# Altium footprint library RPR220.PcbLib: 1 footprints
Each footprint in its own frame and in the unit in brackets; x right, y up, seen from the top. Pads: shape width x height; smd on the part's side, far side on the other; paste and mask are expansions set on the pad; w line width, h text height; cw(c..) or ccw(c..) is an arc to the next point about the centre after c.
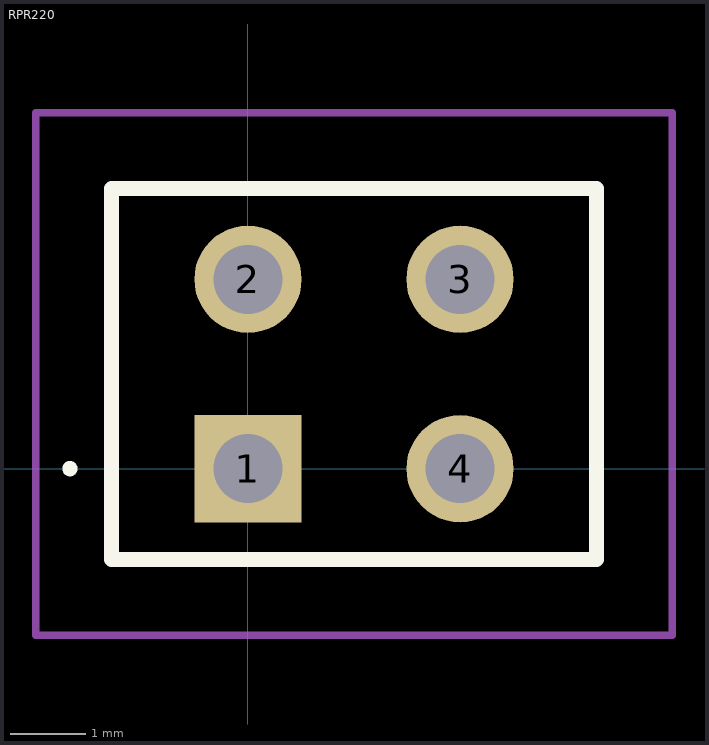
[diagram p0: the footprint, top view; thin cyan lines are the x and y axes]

## RPR220 [mm]
pads (4):
  rect 1.416x1.416 hole 0.91: 1(0,0)
  round 1.416 hole 0.91: 2(0,2.5) 3(2.8,2.5) 4(2.8,0)
Top Overlay:
  lines w0.1: -2.4,0 cw(c-2.35,0) -2.3,0 ; -2.4,0 -2.4,0 ; -2.4,0 ccw(c-2.35,0) -2.3,0 ; -2.3,0 -2.3,0
  lines w0.2: -1.8,-1.2 4.6,-1.2 4.6,3.7 -1.8,3.7 -1.8,-1.2
Mechanical 15:
  lines w0.1: -1.8,-1.2 4.6,-1.2 4.6,3.7 -1.8,3.7 -1.8,-1.2
Mechanical 20:
  lines w0.1: -2.8,-2.2 5.6,-2.2 5.6,4.7 -2.8,4.7 -2.8,-2.2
